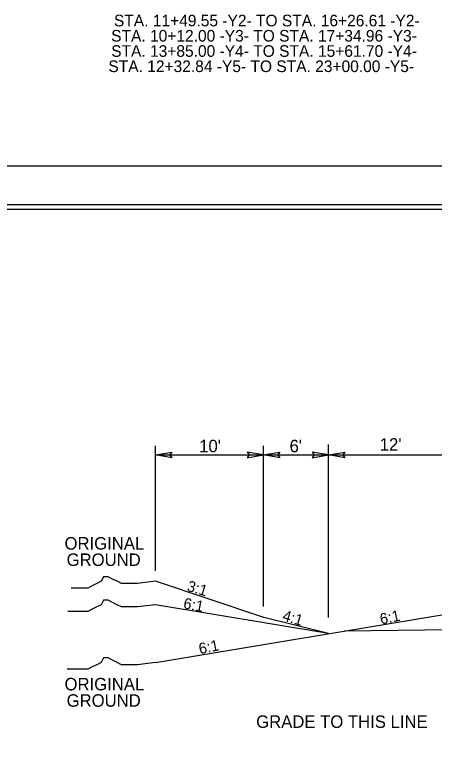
# Model space of a CAD drawing. Extents: x 2176156 to 2177167, y 76401 to 76644.
# Drawn here: x 2176720.1 to 2176758.9, y 76577.2 to 76644.5 of the extents above; entities that cross this region are included whole.
import ezdxf

# ---------------------------------------------------------------- set-up
doc = ezdxf.new("R2010")
doc.units = 0
for name, color, linetype in [('Exist Building', 7, 'Continuous'), ('Exist Roads Curbs', 7, 'Continuous'), ('Exist Roads EOP Other', 7, 'Continuous'), ('Exist Roads Soil', 7, 'Continuous'), ('Exist Structure Minor Culvert Topo', 7, 'Continuous'), ('Exist Vegetation Woods Line', 7, 'Continuous'), ('Old_Level_1', 7, 'Continuous'), ('Old_Level_3', 7, 'Continuous'), ('Sheet Cutting Line CELL', 7, 'Continuous'), ('Sheet Data Field CELL', 7, 'Continuous'), ('Sheet Plot Border Outside CELL', 7, 'Continuous'), ('Sheet Sticker Exception Certification CELL', 7, 'Continuous')]:
    doc.layers.add(name, color=color, linetype=linetype)

msp = doc.modelspace()

# ---------------------------------------------------------------- linework, layer by layer
at = {"layer": 'Exist Building'}
msp.add_line((2176750.611, 76587.518), (2176780.289, 76587.96), dxfattribs=at)
at = {"layer": 'Exist Roads Curbs'}
for points in [[(2176733.159, 76592.11), (2176731.488, 76591.902), (2176731.07, 76591.902), (2176730.443, 76591.902), (2176730.025, 76591.902), (2176729.608, 76592.11), (2176729.19, 76592.319), (2176728.772, 76592.529), (2176728.355, 76592.529), (2176728.145, 76592.11), (2176727.727, 76591.902), (2176727.31, 76591.692), (2176726.892, 76591.484), (2176726.474, 76591.484), (2176726.057, 76591.484), (2176725.639, 76591.484), (2176725.368, 76591.484)], [(2176733.158, 76589.943), (2176731.488, 76589.735), (2176731.07, 76589.735), (2176730.443, 76589.735), (2176730.025, 76589.735), (2176729.607, 76589.943), (2176729.19, 76590.153), (2176728.772, 76590.362), (2176728.354, 76590.362), (2176728.145, 76589.943), (2176727.727, 76589.735), (2176727.309, 76589.525), (2176726.892, 76589.317), (2176726.474, 76589.317), (2176726.056, 76589.317), (2176725.639, 76589.317), (2176725.221, 76589.317), (2176725.058, 76589.317)], [(2176733.159, 76584.61), (2176731.488, 76584.402), (2176731.07, 76584.402), (2176730.443, 76584.402), (2176730.025, 76584.402), (2176729.608, 76584.61), (2176729.19, 76584.819), (2176728.772, 76585.029), (2176728.355, 76585.029), (2176728.145, 76584.61), (2176727.727, 76584.402), (2176727.31, 76584.192), (2176726.892, 76583.984), (2176726.474, 76583.984), (2176726.057, 76583.984), (2176725.639, 76583.984), (2176725.221, 76583.984), (2176724.981, 76583.984)]]:
    msp.add_lwpolyline(points, dxfattribs=at)
at = {"layer": 'Exist Roads EOP Other'}
for p, q in [((2176743.159, 76588.776), (2176733.159, 76592.11)), ((2176749.159, 76587.276), (2176743.159, 76588.776))]:
    msp.add_line(p, q, dxfattribs=at)
at = {"layer": 'Exist Roads Soil'}
for p, q in [((2176749.159, 76587.276), (2176733.159, 76589.943)), ((2176733.159, 76584.61), (2176761.111, 76589.268))]:
    msp.add_line(p, q, dxfattribs=at)
at = {"layer": 'Old_Level_1'}
for points in [[(2176734.655, 76603.52), (2176733.146, 76603.78), (2176734.664, 76604.048), (2176734.471, 76603.78)], [(2176741.636, 76603.52), (2176743.146, 76603.78), (2176741.628, 76604.048), (2176741.821, 76603.78)], [(2176744.655, 76603.52), (2176743.146, 76603.78), (2176744.664, 76604.048), (2176744.471, 76603.78)], [(2176747.636, 76603.52), (2176749.146, 76603.78), (2176747.628, 76604.048), (2176747.821, 76603.78)], [(2176750.655, 76603.52), (2176749.146, 76603.78), (2176750.664, 76604.048), (2176750.471, 76603.78)]]:
    msp.add_lwpolyline(points, close=True, dxfattribs=at)
at = {"layer": 'Old_Level_3'}
for p, q in [((2176733.146, 76593.072), (2176733.146, 76604.612)), ((2176743.146, 76589.77), (2176743.146, 76604.612)), ((2176749.146, 76588.752), (2176749.146, 76604.745)), ((2176733.146, 76603.78), (2176797.146, 76603.78))]:
    msp.add_line(p, q, dxfattribs=at)
at = {"layer": 'Sheet Cutting Line CELL'}
msp.add_lwpolyline([(2176898.707, 76630.475), (2176629.267, 76630.475), (2176629.267, 76454.475), (2176898.707, 76454.475)], close=True, dxfattribs=at)
at = {"layer": 'Sheet Data Field CELL'}
msp.add_lwpolyline([(2176895.987, 76626.475), (2176655.987, 76626.475), (2176655.987, 76458.475), (2176895.987, 76458.475)], close=True, dxfattribs=at)
at = {"layer": 'Sheet Plot Border Outside CELL'}
msp.add_lwpolyline([(2176897.987, 76626.883), (2176631.347, 76626.883), (2176631.347, 76458.067), (2176897.987, 76458.067)], close=True, dxfattribs=at)
at = {"layer": 'Sheet Sticker Exception Certification CELL'}
msp.add_line((2176898.707, 76630.475), (2176629.267, 76630.475), dxfattribs=at)

# ---------------------------------------------------------------- texts
at = {"layer": 'Exist Roads Curbs'}
for s, rotation, p in [('3:1', 343.53506, (2176735.994, 76591.242)), ('6:1', 349.18318, (2176735.675, 76589.614)), ('4:1', 343.53506, (2176744.826, 76588.51)), ('6:1', 11.48655, (2176754.011, 76588.106)), ('6:1', 11.48655, (2176737.261, 76585.365))]:
    msp.add_text(s, height=1.0064, rotation=rotation, dxfattribs=at).set_placement(p)
at = {"layer": 'Exist Structure Minor Culvert Topo'}
for s, height, p in [("10'", 1.1533, (2176737.198, 76604.032)), ("6'", 1.1533, (2176745.552, 76604.032)), ("12' ", 1.1533, (2176753.891, 76604.175)), ('ORIGINAL', 1.1533, (2176724.745, 76595.036)), ('GROUND', 1.1533, (2176724.939, 76593.524)), ('ORIGINAL', 1.1533, (2176724.745, 76582.027)), ('GROUND', 1.1533, (2176724.939, 76580.515)), ('GRADE TO THIS LINE', 1.15334, (2176742.466, 76578.56))]:
    msp.add_text(s, height=height, dxfattribs=at).set_placement(p)
at = {"layer": 'Exist Vegetation Woods Line'}
for s, p in [('STA. 11+49.55 -Y2- TO STA. 16+26.61 -Y2-', (2176729.315, 76643.391)), ('STA. 10+12.00 -Y3- TO STA. 17+34.96 -Y3-', (2176729.058, 76641.983)), ('STA. 13+85.00 -Y4- TO STA. 15+61.70 -Y4-', (2176729.058, 76640.575)), ('STA. 12+32.84 -Y5- TO STA. 23+00.00 -Y5-', (2176728.801, 76639.167))]:
    msp.add_text(s, height=1.0742, dxfattribs=at).set_placement(p)

doc.saveas('drawing.dxf')
